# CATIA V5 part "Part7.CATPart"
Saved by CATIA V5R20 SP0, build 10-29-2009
Part number: 9FP1406M5
Revision: ANY
Definition: UNKNOWN
Nomenclature: 9FP1406M5
Source: Unknown
Bounding box of the stored display mesh (mm): x -6.727 to 6.727, y 0 to 6, z -6.9 to 6.9
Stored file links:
  C:\Users\Utente\Desktop\IO LAVORO\3D X SITO CF\CUMSA\3D files PW\pw081030\pw081030_injection\Part7.CATPart
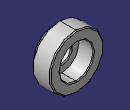
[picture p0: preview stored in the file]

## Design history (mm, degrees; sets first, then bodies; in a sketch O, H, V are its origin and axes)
Body1 "Chaflán1" (main body)
  Solid1: solid without history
